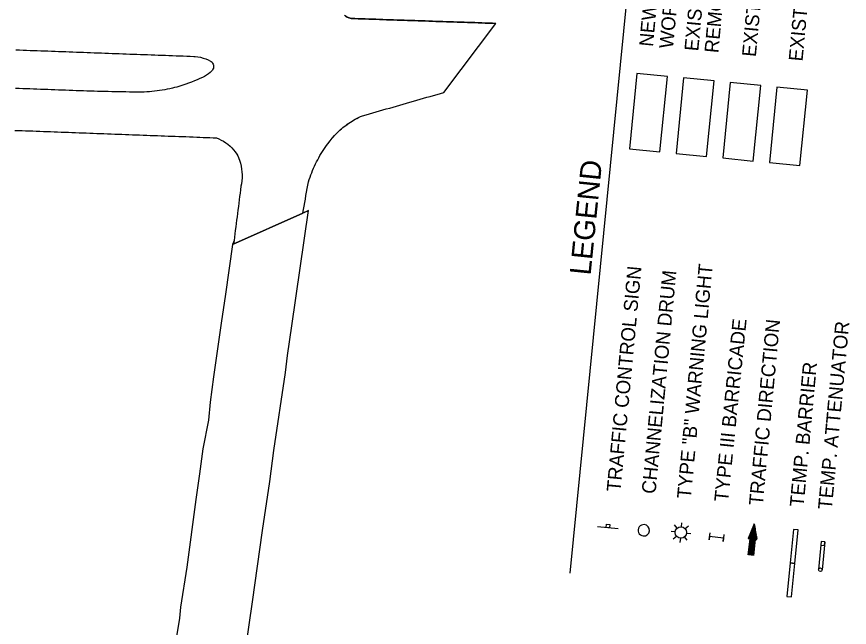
# Model space of a CAD drawing. Extents: x 1795987 to 1799700, y 243690 to 251545.
# Drawn here: x 1797508.8 to 1797973.5, y 245413.3 to 245754 of the extents above; entities that cross this region are included whole.
import ezdxf

# ---------------------------------------------------------------- set-up
doc = ezdxf.new("R2010")
doc.units = 0
for name, color, linetype in [('LEGEND', 7, 'Continuous'), ('Level 23', 7, 'Continuous'), ('Level 62', 7, 'Continuous')]:
    doc.layers.add(name, color=color, linetype=linetype)

# ---------------------------------------------------------------- blocks, each defined once
blk = doc.blocks.new('T21LR')
at = {"layer": 'Level 23'}
for p, q in [((0, 2), (31.5, 2)), ((0, -2), (31.5, -2))]:
    blk.add_line(p, q, dxfattribs=at)
blk.add_lwpolyline([(0, -2), (4, -2), (4, 2), (0, 2)], close=True, dxfattribs=at)
blk.add_circle((31.5, 0), 2, dxfattribs=at)

msp = doc.modelspace()

# ---------------------------------------------------------------- linework, layer by layer
at = {"layer": 'LEGEND'}
for p, q in [((1797817.74, 245443.45), (1797861.68, 245886.96)), ((1797877.46, 245468.63), (1797875.99, 245470.41)), ((1797879.8, 245469.34), (1797880.02, 245471.64)), ((1797920.43, 245471.1), (1797916.98, 245462.78)), ((1797921.95, 245462.22), (1797920.43, 245471.1)), ((1797844.52, 245468.23), (1797832.88, 245469.38)), ((1797876.3, 245466.47), (1797874, 245466.7)), ((1797883.74, 245469.65), (1797881.95, 245468.18)), ((1797882.66, 245465.84), (1797884.96, 245465.61)), ((1797875.22, 245462.67), (1797877.01, 245464.13)), ((1797879.17, 245462.98), (1797878.94, 245460.68)), ((1797882.97, 245461.9), (1797881.51, 245463.69)), ((1797917.92, 245462.67), (1797916.9, 245453.65)), ((1797916.98, 245462.78), (1797917.92, 245462.67)), ((1797920, 245453.3), (1797921.02, 245462.33)), ((1797921.02, 245462.33), (1797921.95, 245462.22))]:
    msp.add_line(p, q, dxfattribs=at)
for points in [[(1797867.8, 245678.59), (1797871.97, 245720.66), (1797854.98, 245722.34), (1797850.81, 245680.28)], [(1797893.84, 245676.01), (1797898, 245718.08), (1797881.02, 245719.76), (1797876.85, 245677.7)], [(1797919.87, 245673.43), (1797924.04, 245715.5), (1797907.05, 245717.18), (1797902.88, 245675.12)], [(1797945.91, 245670.85), (1797950.08, 245712.92), (1797933.09, 245714.61), (1797928.92, 245672.54)], [(1797837.73, 245468.9), (1797837.92, 245470.84), (1797839.86, 245470.65), (1797839.67, 245468.71)], [(1797944.86, 245467.59), (1797942.37, 245467.84), (1797940.52, 245449.18), (1797943.01, 245448.93)], [(1797943.01, 245448.93), (1797940.52, 245449.18), (1797938.68, 245430.52), (1797941.17, 245430.27)]]:
    msp.add_lwpolyline(points, close=True, dxfattribs=at)
for points in [[(1797919.94, 245469.91), (1797918.1, 245453.51)], [(1797920.3, 245470.77), (1797918.36, 245453.49)], [(1797920.53, 245470.52), (1797918.61, 245453.46)], [(1797903.5, 245465.04), (1797903.05, 245461.16), (1797903.28, 245463.1), (1797895.53, 245464), (1797895.3, 245462.06), (1797895.75, 245465.94)], [(1797918.5, 245466.45), (1797917.06, 245453.63)], [(1797918.86, 245467.32), (1797917.32, 245453.6)], [(1797919.22, 245468.18), (1797917.58, 245453.57)], [(1797918.15, 245465.59), (1797917.82, 245462.68)], [(1797919.58, 245469.05), (1797917.84, 245453.54)], [(1797920.69, 245469.6), (1797918.87, 245453.43)], [(1797920.85, 245468.68), (1797919.13, 245453.4)], [(1797921.01, 245467.75), (1797919.39, 245453.37)], [(1797921.16, 245466.83), (1797919.65, 245453.34)], [(1797921.32, 245465.91), (1797919.91, 245453.31)], [(1797917.07, 245463), (1797917.04, 245462.77)], [(1797917.43, 245463.86), (1797917.3, 245462.74)], [(1797917.79, 245464.72), (1797917.56, 245462.71)], [(1797921.48, 245464.99), (1797921.18, 245462.31)], [(1797921.64, 245464.06), (1797921.44, 245462.28)], [(1797921.8, 245463.14), (1797921.7, 245462.25)]]:
    msp.add_lwpolyline(points, dxfattribs=at)
msp.add_circle((1797879.48, 245466.16), 3.19, dxfattribs=at)
for start, end in [(84.3414, 264.3414), (264.3414, 84.3414)]:
    msp.add_arc((1797858.72, 245467.4), 3.18, start, end, dxfattribs=at)
at = {"layer": 'Level 62'}
for p, q in [((1797693.32, 245753.7), (1797691.74, 245754.71)), ((1797695.47, 245752.96), (1797693.32, 245753.7)), ((1797697.44, 245752.89), (1797695.47, 245752.96)), ((1797699.41, 245752.82), (1797697.44, 245752.89)), ((1797701.38, 245752.76), (1797699.41, 245752.82)), ((1797703.35, 245752.69), (1797701.38, 245752.76)), ((1797705.32, 245752.62), (1797703.35, 245752.69)), ((1797707.29, 245752.56), (1797705.32, 245752.62)), ((1797709.26, 245752.49), (1797707.29, 245752.56)), ((1797711.23, 245752.42), (1797709.26, 245752.49)), ((1797713.2, 245752.36), (1797711.23, 245752.42)), ((1797715.17, 245752.29), (1797713.2, 245752.36)), ((1797717.14, 245752.22), (1797715.17, 245752.29)), ((1797719.11, 245752.16), (1797717.14, 245752.22)), ((1797721.08, 245752.09), (1797719.11, 245752.16)), ((1797723.05, 245752.02), (1797721.08, 245752.09)), ((1797725.02, 245751.96), (1797723.05, 245752.02)), ((1797726.99, 245751.89), (1797725.02, 245751.96)), ((1797728.96, 245751.82), (1797726.99, 245751.89)), ((1797730.94, 245751.76), (1797728.96, 245751.82)), ((1797732.91, 245751.69), (1797730.94, 245751.76)), ((1797734.88, 245751.63), (1797732.91, 245751.69)), ((1797736.85, 245751.56), (1797734.88, 245751.63)), ((1797738.82, 245751.49), (1797736.85, 245751.56)), ((1797740.79, 245751.43), (1797738.82, 245751.49)), ((1797742.76, 245751.36), (1797740.79, 245751.43)), ((1797744.73, 245751.29), (1797742.76, 245751.36)), ((1797746.7, 245751.23), (1797744.73, 245751.29)), ((1797748.67, 245751.16), (1797746.7, 245751.23)), ((1797747.18, 245711.68), (1797776.25, 245750.23)), ((1797747.18, 245711.68), (1797776.25, 245750.23)), ((1797750.64, 245751.09), (1797748.67, 245751.16)), ((1797752.61, 245751.03), (1797750.64, 245751.09)), ((1797754.58, 245750.96), (1797752.61, 245751.03)), ((1797756.55, 245750.89), (1797754.58, 245750.96)), ((1797758.52, 245750.83), (1797756.55, 245750.89)), ((1797760.49, 245750.76), (1797758.52, 245750.83)), ((1797762.46, 245750.69), (1797760.49, 245750.76)), ((1797764.43, 245750.63), (1797762.46, 245750.69)), ((1797766.4, 245750.56), (1797764.43, 245750.63)), ((1797768.37, 245750.49), (1797766.4, 245750.56)), ((1797770.34, 245750.43), (1797768.37, 245750.49)), ((1797772.31, 245750.36), (1797770.34, 245750.43)), ((1797774.28, 245750.29), (1797772.31, 245750.36)), ((1797776.25, 245750.23), (1797774.28, 245750.29)), ((1797745.3, 245711.14), (1797747.18, 245711.68)), ((1797728.31, 245706.26), (1797730.2, 245706.81)), ((1797730.2, 245706.81), (1797732.09, 245707.35)), ((1797732.09, 245707.35), (1797733.97, 245707.89)), ((1797733.97, 245707.89), (1797735.86, 245708.43)), ((1797735.86, 245708.43), (1797737.75, 245708.97)), ((1797737.75, 245708.97), (1797739.63, 245709.52)), ((1797739.63, 245709.52), (1797741.52, 245710.06)), ((1797741.52, 245710.06), (1797743.41, 245710.6)), ((1797743.41, 245710.6), (1797745.3, 245711.14)), ((1797713.22, 245701.93), (1797715.1, 245702.47)), ((1797715.1, 245702.47), (1797716.99, 245703.01)), ((1797716.99, 245703.01), (1797718.88, 245703.55)), ((1797718.88, 245703.55), (1797720.76, 245704.1)), ((1797720.76, 245704.1), (1797722.65, 245704.64)), ((1797722.65, 245704.64), (1797724.54, 245705.18)), ((1797724.54, 245705.18), (1797726.43, 245705.72)), ((1797726.43, 245705.72), (1797728.31, 245706.26)), ((1797697.79, 245696.72), (1797699.66, 245697.68)), ((1797699.66, 245697.68), (1797700.77, 245698.18)), ((1797700.77, 245698.18), (1797701.89, 245698.68)), ((1797701.89, 245698.68), (1797703.78, 245699.22)), ((1797703.78, 245699.22), (1797705.67, 245699.76)), ((1797705.67, 245699.76), (1797707.56, 245700.3)), ((1797707.56, 245700.3), (1797709.44, 245700.84)), ((1797709.44, 245700.84), (1797711.33, 245701.39)), ((1797711.33, 245701.39), (1797713.22, 245701.93)), ((1797690.82, 245692.05), (1797692.48, 245693.34)), ((1797692.48, 245693.34), (1797694.19, 245694.55)), ((1797694.19, 245694.55), (1797695.96, 245695.68)), ((1797695.96, 245695.68), (1797697.79, 245696.72)), ((1797507.82, 245690.55), (1797509.81, 245690.48)), ((1797509.81, 245690.48), (1797511.8, 245690.41)), ((1797511.8, 245690.41), (1797513.79, 245690.33)), ((1797513.79, 245690.33), (1797515.78, 245690.26)), ((1797515.78, 245690.26), (1797517.77, 245690.19)), ((1797517.77, 245690.19), (1797519.76, 245690.11)), ((1797519.76, 245690.11), (1797521.75, 245690.04)), ((1797521.75, 245690.04), (1797523.74, 245689.97)), ((1797523.74, 245689.97), (1797525.72, 245689.89)), ((1797525.72, 245689.89), (1797527.71, 245689.82)), ((1797527.71, 245689.82), (1797529.7, 245689.75)), ((1797529.7, 245689.75), (1797531.69, 245689.67)), ((1797531.69, 245689.67), (1797533.68, 245689.6)), ((1797533.68, 245689.6), (1797535.67, 245689.52)), ((1797535.67, 245689.52), (1797537.66, 245689.45)), ((1797537.66, 245689.45), (1797539.65, 245689.38)), ((1797539.65, 245689.38), (1797541.64, 245689.3)), ((1797541.64, 245689.3), (1797543.63, 245689.23)), ((1797543.63, 245689.23), (1797545.62, 245689.16)), ((1797545.62, 245689.16), (1797547.6, 245689.08)), ((1797547.6, 245689.08), (1797549.59, 245689.01)), ((1797549.59, 245689.01), (1797551.58, 245688.94)), ((1797551.58, 245688.94), (1797553.57, 245688.86)), ((1797553.57, 245688.86), (1797555.56, 245688.79)), ((1797555.56, 245688.79), (1797557.55, 245688.72)), ((1797557.55, 245688.72), (1797559.54, 245688.64)), ((1797559.54, 245688.64), (1797561.53, 245688.57)), ((1797561.53, 245688.57), (1797563.52, 245688.5)), ((1797563.52, 245688.5), (1797565.51, 245688.42)), ((1797565.51, 245688.42), (1797567.49, 245688.35)), ((1797567.49, 245688.35), (1797569.48, 245688.28)), ((1797569.48, 245688.28), (1797571.47, 245688.2)), ((1797571.47, 245688.2), (1797573.46, 245688.13)), ((1797686.25, 245687.73), (1797687.71, 245689.24)), ((1797687.71, 245689.24), (1797689.23, 245690.68)), ((1797689.23, 245690.68), (1797690.82, 245692.05)), ((1797573.46, 245688.13), (1797575.45, 245688.06)), ((1797575.45, 245688.06), (1797577.44, 245687.98)), ((1797577.44, 245687.98), (1797579.43, 245687.91)), ((1797579.43, 245687.91), (1797581.42, 245687.84)), ((1797581.42, 245687.84), (1797583.41, 245687.76)), ((1797583.41, 245687.76), (1797585.4, 245687.69)), ((1797585.4, 245687.69), (1797587.39, 245687.61)), ((1797587.39, 245687.61), (1797589.37, 245687.54)), ((1797589.37, 245687.54), (1797591.36, 245687.47)), ((1797591.36, 245687.47), (1797593.35, 245687.39)), ((1797593.35, 245687.39), (1797595.34, 245687.32)), ((1797595.34, 245687.32), (1797597.33, 245687.25)), ((1797597.33, 245687.25), (1797599.32, 245687.17)), ((1797599.32, 245687.17), (1797601.31, 245687.1)), ((1797601.31, 245687.1), (1797603.3, 245687.03)), ((1797603.3, 245687.03), (1797605.29, 245686.95)), ((1797605.29, 245686.95), (1797607.28, 245686.88)), ((1797607.28, 245686.88), (1797609.27, 245686.81)), ((1797609.27, 245686.81), (1797611.11, 245686.72)), ((1797611.11, 245686.72), (1797612.95, 245686.64)), ((1797612.95, 245686.64), (1797614.79, 245686.56)), ((1797614.79, 245686.56), (1797616.63, 245686.48)), ((1797616.63, 245686.48), (1797618.47, 245686.39)), ((1797618.47, 245686.39), (1797620.31, 245686.31)), ((1797620.31, 245686.31), (1797621.69, 245685.78)), ((1797621.69, 245685.78), (1797623.03, 245685.15)), ((1797623.03, 245685.15), (1797624.32, 245684.44)), ((1797624.32, 245684.44), (1797625.56, 245683.64)), ((1797625.56, 245683.64), (1797626.74, 245682.75)), ((1797682.48, 245683.11), (1797683.68, 245684.63)), ((1797683.68, 245684.63), (1797684.87, 245686.15)), ((1797684.87, 245686.15), (1797686.25, 245687.73)), ((1797626.74, 245682.75), (1797627.87, 245681.79)), ((1797627.87, 245681.79), (1797628.92, 245680.76)), ((1797628.92, 245680.76), (1797629.9, 245679.66)), ((1797629.9, 245679.66), (1797630.81, 245678.49)), ((1797679.47, 245678.73), (1797680.2, 245679.84)), ((1797680.2, 245679.84), (1797680.93, 245680.95)), ((1797680.93, 245680.95), (1797681.71, 245682.03)), ((1797681.71, 245682.03), (1797682.48, 245683.11)), ((1797630.81, 245678.49), (1797631.63, 245677.26)), ((1797631.63, 245677.26), (1797632.15, 245676.33)), ((1797632.15, 245676.33), (1797633.24, 245673.82)), ((1797676.8, 245674.14), (1797677.45, 245675.3)), ((1797677.45, 245675.3), (1797678.09, 245676.46)), ((1797678.09, 245676.46), (1797678.78, 245677.6)), ((1797678.78, 245677.6), (1797679.47, 245678.73)), ((1797633.24, 245673.82), (1797633.71, 245672.23)), ((1797633.71, 245672.23), (1797634.08, 245670.61)), ((1797634.08, 245670.61), (1797634.35, 245668.97)), ((1797674.49, 245669.36), (1797675.04, 245670.57)), ((1797675.04, 245670.57), (1797675.6, 245671.77)), ((1797675.6, 245671.77), (1797676.2, 245672.96)), ((1797676.2, 245672.96), (1797676.8, 245674.14)), ((1797634.35, 245668.97), (1797634.53, 245667.31)), ((1797634.53, 245667.31), (1797634.6, 245665.65)), ((1797634.6, 245665.65), (1797634.58, 245663.99)), ((1797672.54, 245664.42), (1797673, 245665.66)), ((1797673, 245665.66), (1797673.47, 245666.91)), ((1797673.47, 245666.91), (1797673.98, 245668.13)), ((1797673.98, 245668.13), (1797674.49, 245669.36)), ((1797634.22, 245660.69), (1797633.96, 245659.33)), ((1797634.45, 245662.33), (1797634.22, 245660.69)), ((1797634.58, 245663.99), (1797634.45, 245662.33)), ((1797671.35, 245659.95), (1797671.7, 245661.9)), ((1797671.7, 245661.9), (1797672.12, 245663.16)), ((1797672.12, 245663.16), (1797672.54, 245664.42)), ((1797633.72, 245657.44), (1797633.48, 245655.55)), ((1797633.96, 245659.33), (1797633.72, 245657.44)), ((1797670.27, 245654.12), (1797670.63, 245656.06)), ((1797670.63, 245656.06), (1797670.99, 245658.01)), ((1797670.99, 245658.01), (1797671.35, 245659.95)), ((1797633, 245651.76), (1797632.76, 245649.87)), ((1797633.24, 245653.65), (1797633, 245651.76)), ((1797633.48, 245655.55), (1797633.24, 245653.65)), ((1797669.56, 245650.23), (1797669.92, 245652.17)), ((1797669.92, 245652.17), (1797670.27, 245654.12)), ((1797632.52, 245647.98), (1797632.28, 245646.09)), ((1797632.76, 245649.87), (1797632.52, 245647.98)), ((1797668.49, 245644.39), (1797668.85, 245646.34)), ((1797668.85, 245646.34), (1797669.2, 245648.28)), ((1797669.2, 245648.28), (1797669.56, 245650.23)), ((1797629.32, 245626.92), (1797671.67, 245645.81)), ((1797629.32, 245626.92), (1797668.49, 245644.39)), ((1797631.79, 245642.31), (1797631.55, 245640.41)), ((1797632.04, 245644.2), (1797631.79, 245642.31)), ((1797632.28, 245646.09), (1797632.04, 245644.2)), ((1797631.31, 245638.52), (1797631.07, 245636.63)), ((1797631.55, 245640.41), (1797631.31, 245638.52)), ((1797630.59, 245632.85), (1797630.35, 245630.96)), ((1797630.83, 245634.74), (1797630.59, 245632.85)), ((1797631.07, 245636.63), (1797630.83, 245634.74)), ((1797630.11, 245629.07), (1797629.32, 245626.92)), ((1797630.35, 245630.96), (1797630.11, 245629.07))]:
    msp.add_line(p, q, dxfattribs=at)
for points in [[(1797692.5, 245754.17), (1797693.32, 245753.7), (1797694.18, 245753.33), (1797695.47, 245752.96), (1797697.44, 245752.89), (1797699.41, 245752.82), (1797701.38, 245752.76), (1797703.35, 245752.69), (1797705.32, 245752.62), (1797707.29, 245752.56), (1797709.26, 245752.49), (1797711.23, 245752.42), (1797713.2, 245752.36), (1797715.17, 245752.29), (1797717.14, 245752.22), (1797719.11, 245752.16), (1797721.08, 245752.09), (1797723.05, 245752.02), (1797725.02, 245751.96), (1797726.99, 245751.89), (1797728.96, 245751.82), (1797730.94, 245751.76), (1797732.91, 245751.69), (1797734.88, 245751.63), (1797736.85, 245751.56), (1797738.82, 245751.49), (1797740.79, 245751.43), (1797742.76, 245751.36), (1797744.73, 245751.29), (1797746.7, 245751.23), (1797748.67, 245751.16), (1797750.64, 245751.09), (1797752.61, 245751.03), (1797754.58, 245750.96), (1797756.55, 245750.89), (1797758.52, 245750.83), (1797760.49, 245750.76), (1797762.46, 245750.69), (1797764.43, 245750.63), (1797766.4, 245750.56), (1797768.37, 245750.49), (1797770.34, 245750.43), (1797772.31, 245750.36), (1797774.28, 245750.29), (1797776.25, 245750.23)], [(1797508.39, 245735.47), (1797510.37, 245735.4), (1797512.36, 245735.33), (1797514.35, 245735.26), (1797516.33, 245735.18), (1797518.32, 245735.11), (1797520.31, 245735.04), (1797522.29, 245734.96), (1797524.28, 245734.89), (1797526.27, 245734.82), (1797528.25, 245734.74), (1797530.24, 245734.67), (1797532.23, 245734.6), (1797534.21, 245734.52), (1797536.2, 245734.45), (1797538.19, 245734.38), (1797540.17, 245734.31), (1797542.16, 245734.23), (1797544.15, 245734.16), (1797546.13, 245734.09), (1797548.12, 245734.01), (1797550.11, 245733.94), (1797552.09, 245733.87), (1797554.08, 245733.79), (1797556.07, 245733.72), (1797558.05, 245733.65), (1797560.04, 245733.58), (1797562.03, 245733.5), (1797564.01, 245733.43), (1797566, 245733.36), (1797567.99, 245733.28), (1797569.97, 245733.21), (1797571.96, 245733.14), (1797573.95, 245733.06), (1797575.93, 245732.99), (1797577.92, 245732.92), (1797579.91, 245732.84), (1797581.89, 245732.77), (1797583.88, 245732.7), (1797585.87, 245732.63), (1797587.85, 245732.55), (1797589.84, 245732.48), (1797591.83, 245732.41), (1797593.81, 245732.33), (1797595.8, 245732.26), (1797597.78, 245732.19), (1797599.77, 245732.11), (1797601.76, 245732.04), (1797603.74, 245731.97), (1797605.73, 245731.89), (1797607.72, 245731.82), (1797608.49, 245731.76), (1797609.97, 245731.58), (1797611.44, 245731.29), (1797612.88, 245730.9), (1797614.3, 245730.43), (1797615.68, 245729.85), (1797617.02, 245729.19), (1797617.4, 245728.92), (1797617.83, 245728.52), (1797618.18, 245728.05), (1797618.45, 245727.52), (1797618.63, 245726.96), (1797618.71, 245726.38), (1797618.69, 245725.79), (1797618.58, 245725.21), (1797618.36, 245724.66), (1797618.06, 245724.15), (1797617.67, 245723.7), (1797616.84, 245722.89), (1797615.86, 245722.06), (1797614.82, 245721.3), (1797613.73, 245720.63), (1797612.58, 245720.05), (1797611.05, 245719.4), (1797609.52, 245718.75), (1797607.99, 245718.11), (1797606.38, 245717.49), (1797604.77, 245716.87), (1797603.14, 245716.31), (1797601.51, 245715.74), (1797599.86, 245715.22), (1797598.22, 245714.69), (1797596.97, 245714.38), (1797595.72, 245714.06), (1797594.31, 245713.76), (1797592.89, 245713.45), (1797591.47, 245713.19), (1797590.05, 245712.93), (1797588.61, 245712.72), (1797587.18, 245712.51), (1797585.74, 245712.35), (1797584.3, 245712.19), (1797582.86, 245712.08), (1797581.42, 245711.96), (1797579.97, 245711.9), (1797578.52, 245711.84), (1797577.07, 245711.83), (1797575.63, 245711.82), (1797573.66, 245711.86), (1797571.7, 245711.9), (1797569.73, 245711.94), (1797567.77, 245711.99), (1797565.8, 245712.03), (1797563.84, 245712.07), (1797561.88, 245712.11), (1797559.91, 245712.15), (1797557.95, 245712.19), (1797555.98, 245712.23), (1797554.02, 245712.27), (1797552.05, 245712.32), (1797550.06, 245712.39), (1797548.07, 245712.46), (1797546.07, 245712.54), (1797544.08, 245712.61), (1797542.09, 245712.68), (1797540.09, 245712.76), (1797538.1, 245712.83), (1797536.11, 245712.9), (1797534.11, 245712.98), (1797532.12, 245713.05), (1797530.13, 245713.12), (1797528.13, 245713.2), (1797526.14, 245713.27), (1797524.15, 245713.35), (1797522.15, 245713.42), (1797520.16, 245713.49), (1797518.17, 245713.57), (1797516.18, 245713.64), (1797514.18, 245713.71), (1797512.19, 245713.79), (1797510.2, 245713.86), (1797508.2, 245713.93)], [(1797902.88, 245675.12), (1797919.87, 245673.43), (1797924.04, 245715.5), (1797907.05, 245717.18), (1797902.88, 245675.12)], [(1797668.49, 245644.39), (1797668.85, 245646.34), (1797669.2, 245648.28), (1797669.56, 245650.23), (1797669.92, 245652.17), (1797670.27, 245654.12), (1797670.63, 245656.06), (1797670.99, 245658.01), (1797671.35, 245659.95), (1797671.7, 245661.9), (1797672.12, 245663.16), (1797672.54, 245664.42), (1797673, 245665.66), (1797673.47, 245666.91), (1797673.98, 245668.13), (1797674.49, 245669.36), (1797675.04, 245670.57), (1797675.6, 245671.77), (1797676.2, 245672.96), (1797676.8, 245674.14), (1797677.45, 245675.3), (1797678.09, 245676.46), (1797678.78, 245677.6), (1797679.47, 245678.73), (1797680.2, 245679.84), (1797680.93, 245680.95), (1797681.71, 245682.03), (1797682.48, 245683.11), (1797683.68, 245684.63), (1797684.87, 245686.15), (1797685.56, 245686.94), (1797686.25, 245687.73), (1797686.98, 245688.49), (1797687.71, 245689.24), (1797688.47, 245689.96), (1797689.23, 245690.68), (1797690.03, 245691.37), (1797690.82, 245692.05), (1797691.65, 245692.7), (1797692.48, 245693.34), (1797693.34, 245693.95), (1797694.19, 245694.55), (1797695.08, 245695.12), (1797695.96, 245695.68), (1797696.87, 245696.2), (1797697.79, 245696.72), (1797698.72, 245697.2), (1797699.66, 245697.68), (1797700.77, 245698.18), (1797701.89, 245698.68), (1797703.78, 245699.22), (1797705.67, 245699.76), (1797707.56, 245700.3), (1797709.44, 245700.84), (1797711.33, 245701.39), (1797713.22, 245701.93), (1797715.1, 245702.47), (1797716.99, 245703.01), (1797718.88, 245703.55), (1797720.76, 245704.1), (1797722.65, 245704.64), (1797724.54, 245705.18), (1797726.43, 245705.72), (1797728.31, 245706.26), (1797730.2, 245706.81), (1797732.09, 245707.35), (1797733.97, 245707.89), (1797735.86, 245708.43), (1797737.75, 245708.97), (1797739.63, 245709.52), (1797741.52, 245710.06), (1797743.41, 245710.6), (1797745.3, 245711.14), (1797747.18, 245711.68)], [(1797507.82, 245690.55), (1797509.81, 245690.48), (1797511.8, 245690.41), (1797513.79, 245690.33), (1797515.78, 245690.26), (1797517.77, 245690.19), (1797519.76, 245690.11), (1797521.75, 245690.04), (1797523.74, 245689.97), (1797525.72, 245689.89), (1797527.71, 245689.82), (1797529.7, 245689.75), (1797531.69, 245689.67), (1797533.68, 245689.6), (1797535.67, 245689.52), (1797537.66, 245689.45), (1797539.65, 245689.38), (1797541.64, 245689.3), (1797543.63, 245689.23), (1797545.62, 245689.16), (1797547.6, 245689.08), (1797549.59, 245689.01), (1797551.58, 245688.94), (1797553.57, 245688.86), (1797555.56, 245688.79), (1797557.55, 245688.72), (1797559.54, 245688.64), (1797561.53, 245688.57), (1797563.52, 245688.5), (1797565.51, 245688.42), (1797567.49, 245688.35), (1797569.48, 245688.28), (1797571.47, 245688.2), (1797573.46, 245688.13), (1797575.45, 245688.06), (1797577.44, 245687.98), (1797579.43, 245687.91), (1797581.42, 245687.84), (1797583.41, 245687.76), (1797585.4, 245687.69), (1797587.39, 245687.61), (1797589.37, 245687.54), (1797591.36, 245687.47), (1797593.35, 245687.39), (1797595.34, 245687.32), (1797597.33, 245687.25), (1797599.32, 245687.17), (1797601.31, 245687.1), (1797603.3, 245687.03), (1797605.29, 245686.95), (1797607.28, 245686.88), (1797609.27, 245686.81), (1797611.11, 245686.72), (1797612.95, 245686.64), (1797614.79, 245686.56), (1797616.63, 245686.48), (1797618.47, 245686.39), (1797620.31, 245686.31), (1797621.69, 245685.78), (1797623.03, 245685.15), (1797624.32, 245684.44), (1797625.56, 245683.64), (1797626.74, 245682.75), (1797627.87, 245681.79), (1797628.92, 245680.76), (1797629.9, 245679.66), (1797630.81, 245678.49), (1797631.63, 245677.26), (1797632.15, 245676.33), (1797632.68, 245675.39), (1797633.24, 245673.82), (1797633.71, 245672.23), (1797634.08, 245670.61), (1797634.35, 245668.97), (1797634.53, 245667.31), (1797634.6, 245665.65), (1797634.58, 245663.99), (1797634.45, 245662.33), (1797634.22, 245660.69), (1797633.96, 245659.33), (1797633.72, 245657.44), (1797633.48, 245655.55), (1797633.24, 245653.65), (1797633, 245651.76), (1797632.76, 245649.87), (1797632.52, 245647.98), (1797632.28, 245646.09), (1797632.04, 245644.2), (1797631.79, 245642.31), (1797631.55, 245640.41), (1797631.31, 245638.52), (1797631.07, 245636.63), (1797630.83, 245634.74), (1797630.59, 245632.85), (1797630.35, 245630.96), (1797630.11, 245629.07), (1797629.87, 245627.17)], [(1797668.49, 245644.39), (1797629.32, 245626.92), (1797625.37, 245599.17), (1797622.91, 245582.88), (1797618.72, 245552.94), (1797616.82, 245538.81), (1797615.92, 245528.8), (1797612.79, 245512.8), (1797610.88, 245498.85), (1797608.73, 245484.63), (1797603.87, 245446.86), (1797600.33, 245424.56), (1797599.68, 245418.39), (1797596.56, 245399.07)], [(1797632.68, 245373.59), (1797640.38, 245427.53), (1797646.03, 245467.33), (1797650.06, 245494.55), (1797652.35, 245511.93), (1797658.75, 245555.41), (1797660.02, 245564.89), (1797662.33, 245581.55), (1797671.67, 245645.81), (1797668.49, 245644.39)]]:
    msp.add_lwpolyline(points, dxfattribs=at)

# ---------------------------------------------------------------- block references
at = {"layer": 'LEGEND', "xscale": 0.5000000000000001, "yscale": 0.5000000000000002, "rotation": -95.50928026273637}
msp.add_blockref('T21LR', (1797958.84, 245461.05), dxfattribs=at)

# ---------------------------------------------------------------- texts
at = {"layer": 'LEGEND'}
for s, height, rotation, p in [('NEW  CONSTRUCTION', 7.7999, 84.6544, (1797863.89, 245736.99)), ('REMOVAL WORK AREA', 7.7999, 84.6544, (1797900.36, 245733.44)), ('EXISTING ROADWAY', 7.7999, 84.6544, (1797889.17, 245734.48)), ('EXISTING PAVEMENT', 7.7999, 84.6544, (1797921.3, 245731.32)), ('EXISTING CONCRETE', 7.7999, 84.6544, (1797947.35, 245728.82)), ('WORK AREA', 7.8, 84.6544, (1797875.08, 245735.94)), ('LEGEND', 11.7, 84.1754, (1797829.06, 245609.39)), ('TRAFFIC CONTROL SIGN', 7.7999, 84.6544, (1797845.77, 245488.67)), ('TYPE "B" WARNING LIGHT', 7.7999, 84.6544, (1797885.02, 245484.78)), ('CHANNELIZATION DRUM', 7.7999, 84.6544, (1797865.33, 245487.48)), ('TYPE III BARRICADE', 7.7999, 84.1754, (1797905.8, 245483.02)), ('TRAFFIC DIRECTION', 7.7999, 84.6544, (1797925.16, 245480.94)), ('TEMP. ATTENUATOR', 7.7999, 84.6544, (1797963.7, 245478.67)), ('TEMP. BARRIER', 7.7999, 84.6544, (1797947.94, 245480.17))]:
    msp.add_text(s, height=height, rotation=rotation, dxfattribs=at).set_placement(p)

doc.saveas('drawing.dxf')
